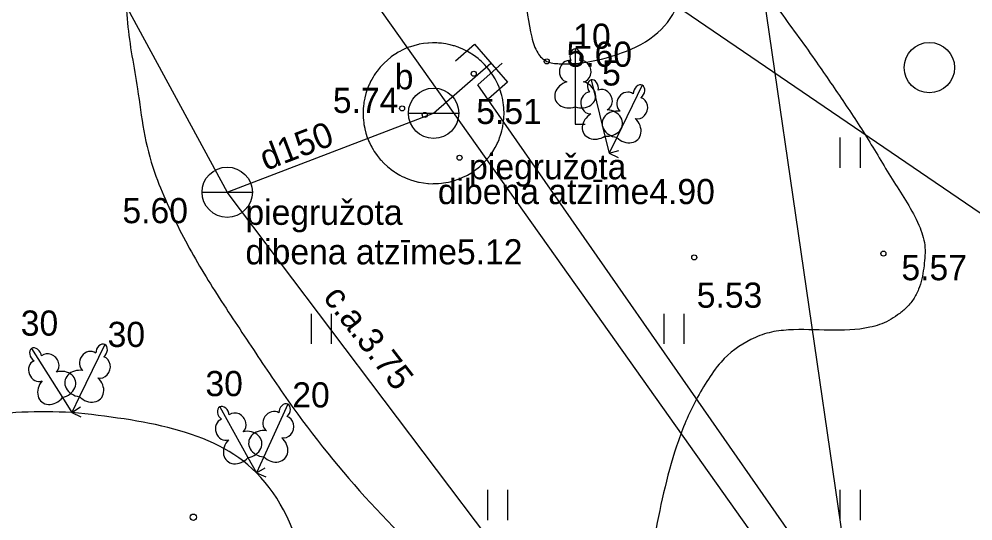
# Model space of a CAD drawing. Extents: x 519536 to 519949, y 326041 to 326519.
# Drawn here: x 519618.19 to 519637.13, y 326371.48 to 326381.46 of the extents above; entities that cross this region are included whole.
import ezdxf

# ---------------------------------------------------------------- set-up
doc = ezdxf.new("R2010")
doc.units = 0
for name, color, linetype in [('APGR_SARK_####_####_#', 7, 'Continuous'), ('BUVE_BDET_####_####_#', 7, 'Continuous'), ('BUVE_BDET_####_TKST_#', 7, 'Continuous'), ('ELEK_VADP_ZSPR_####_#', 7, 'Continuous'), ('RELJ_AATZ_####_TKST_#', 7, 'Continuous'), ('RELJ_ELEM_####_####_#', 7, 'Continuous'), ('RELJ_HORZ_PAMT_####_#', 7, 'Continuous'), ('RELJ_NOGA_####_####_#', 7, 'Continuous'), ('TERT_DIAM_####_TKST_#', 7, 'Continuous'), ('TERT_ELEM_####_####_#', 7, 'Continuous'), ('TERT_KONT_####_####_#', 7, 'Continuous'), ('UDTK_ELEM_####_####_#', 7, 'Continuous'), ('UDTK_ELEM_####_TKST_#', 7, 'Continuous'), ('UDTK_VADP_NEDR_####_#', 7, 'Continuous'), ('UDTK_VADP_UDEN_####_#', 7, 'Continuous'), ('UDTK_VADP_UDEN_TKST_#', 7, 'Continuous')]:
    doc.layers.add(name, color=color, linetype=linetype)

msp = doc.modelspace()

# ---------------------------------------------------------------- linework, layer by layer
at = {"layer": 'APGR_SARK_####_####_#'}
msp.add_line((519627.524, 326419.488), (519634.774, 326369.546), dxfattribs=at)
at = {"layer": 'BUVE_BDET_####_####_#'}
for points in [[(519625.753, 326380.812), (519625.724, 326380.796), (519625.667, 326380.761)], [(519625.843, 326380.857), (519625.802, 326380.838), (519625.753, 326380.812)], [(519625.935, 326380.895), (519625.883, 326380.875), (519625.843, 326380.857)], [(519626.03, 326380.927), (519625.966, 326380.907), (519625.935, 326380.895)], [(519626.126, 326380.952), (519626.051, 326380.933), (519626.03, 326380.927)], [(519626.225, 326380.97), (519626.137, 326380.954), (519626.126, 326380.952)], [(519626.324, 326380.98), (519626.313, 326380.98), (519626.225, 326380.97)], [(519626.424, 326380.983), (519626.402, 326380.984), (519626.324, 326380.98)], [(519626.524, 326380.98), (519626.491, 326380.982), (519626.424, 326380.983)], [(519626.623, 326380.969), (519626.579, 326380.975), (519626.524, 326380.98)], [(519626.721, 326380.951), (519626.667, 326380.963), (519626.623, 326380.969)], [(519626.818, 326380.927), (519626.754, 326380.945), (519626.721, 326380.951)], [(519626.913, 326380.895), (519626.84, 326380.921), (519626.818, 326380.927)], [(519627.006, 326380.857), (519627.006, 326380.857), (519626.924, 326380.892), (519626.913, 326380.895)], [(519627.095, 326380.812), (519627.085, 326380.818), (519627.006, 326380.857)], [(519627.181, 326380.761), (519627.162, 326380.774), (519627.095, 326380.812)], [(519625.507, 326380.642), (519625.442, 326380.582), (519625.434, 326380.574)], [(519625.585, 326380.705), (519625.576, 326380.698), (519625.507, 326380.642), (519625.507, 326380.642)], [(519625.667, 326380.761), (519625.649, 326380.75), (519625.585, 326380.705)], [(519627.263, 326380.704), (519627.236, 326380.724), (519627.181, 326380.761)], [(519627.34, 326380.642), (519627.307, 326380.671), (519627.263, 326380.704)], [(519627.413, 326380.573), (519627.374, 326380.612), (519627.34, 326380.642)], [(519625.366, 326380.5), (519625.324, 326380.449), (519625.304, 326380.423)], [(519625.434, 326380.574), (519625.381, 326380.517), (519625.366, 326380.5)], [(519627.482, 326380.5), (519627.437, 326380.55), (519627.413, 326380.573)], [(519627.545, 326380.423), (519627.496, 326380.484), (519627.482, 326380.5)], [(519625.196, 326380.255), (519625.18, 326380.226), (519625.151, 326380.165)], [(519625.247, 326380.341), (519625.223, 326380.303), (519625.196, 326380.255)], [(519625.304, 326380.423), (519625.271, 326380.378), (519625.247, 326380.341)], [(519627.602, 326380.341), (519627.602, 326380.341), (519627.551, 326380.414), (519627.545, 326380.423)], [(519627.652, 326380.255), (519627.647, 326380.265), (519627.602, 326380.341)], [(519627.697, 326380.165), (519627.688, 326380.186), (519627.652, 326380.255)], [(519625.113, 326380.073), (519625.108, 326380.063), (519625.081, 326379.978), (519625.081, 326379.978)], [(519625.151, 326380.165), (519625.141, 326380.145), (519625.113, 326380.073)], [(519627.735, 326380.073), (519627.724, 326380.104), (519627.697, 326380.165)], [(519627.767, 326379.978), (519627.754, 326380.021), (519627.735, 326380.073)], [(519625.056, 326379.882), (519625.042, 326379.805), (519625.039, 326379.783)], [(519625.081, 326379.978), (519625.058, 326379.892), (519625.056, 326379.882)], [(519627.791, 326379.881), (519627.779, 326379.936), (519627.767, 326379.978)], [(519627.809, 326379.783), (519627.799, 326379.849), (519627.791, 326379.881)], [(519625.028, 326379.684), (519625.025, 326379.628), (519625.025, 326379.584)], [(519625.039, 326379.783), (519625.03, 326379.717), (519625.028, 326379.684)], [(519627.82, 326379.684), (519627.813, 326379.761), (519627.809, 326379.783)], [(519627.824, 326379.584), (519627.821, 326379.673), (519627.82, 326379.684)], [(519625.025, 326379.584), (519625.025, 326379.54), (519625.028, 326379.484)], [(519625.028, 326379.484), (519625.03, 326379.451), (519625.039, 326379.385)], [(519627.809, 326379.385), (519627.813, 326379.407), (519627.82, 326379.484)], [(519627.82, 326379.484), (519627.821, 326379.495), (519627.824, 326379.584)], [(519625.039, 326379.385), (519625.042, 326379.363), (519625.056, 326379.286)], [(519627.791, 326379.287), (519627.799, 326379.319), (519627.809, 326379.385)], [(519625.056, 326379.286), (519625.058, 326379.276), (519625.081, 326379.19)], [(519625.081, 326379.19), (519625.081, 326379.19), (519625.108, 326379.105), (519625.113, 326379.095)], [(519627.735, 326379.095), (519627.754, 326379.147), (519627.767, 326379.19)], [(519627.767, 326379.19), (519627.779, 326379.232), (519627.791, 326379.287)], [(519625.113, 326379.095), (519625.141, 326379.023), (519625.151, 326379.003)], [(519625.151, 326379.003), (519625.18, 326378.942), (519625.196, 326378.913)], [(519625.196, 326378.913), (519625.223, 326378.865), (519625.247, 326378.827)], [(519627.602, 326378.827), (519627.647, 326378.903), (519627.652, 326378.913)], [(519627.652, 326378.913), (519627.688, 326378.982), (519627.697, 326379.003)], [(519627.697, 326379.003), (519627.724, 326379.064), (519627.735, 326379.095)], [(519625.247, 326378.827), (519625.271, 326378.79), (519625.304, 326378.745)], [(519625.304, 326378.745), (519625.324, 326378.719), (519625.366, 326378.668)], [(519627.482, 326378.668), (519627.496, 326378.684), (519627.545, 326378.745)], [(519627.545, 326378.745), (519627.551, 326378.754), (519627.602, 326378.827), (519627.602, 326378.827)], [(519625.366, 326378.668), (519625.381, 326378.651), (519625.434, 326378.594)], [(519625.434, 326378.594), (519625.442, 326378.586), (519625.507, 326378.526)], [(519627.34, 326378.526), (519627.374, 326378.556), (519627.413, 326378.595)], [(519627.413, 326378.595), (519627.437, 326378.618), (519627.482, 326378.668)], [(519625.507, 326378.526), (519625.507, 326378.526), (519625.576, 326378.47), (519625.585, 326378.463)], [(519625.585, 326378.463), (519625.649, 326378.418), (519625.667, 326378.407)], [(519625.667, 326378.407), (519625.724, 326378.372), (519625.753, 326378.356)], [(519625.753, 326378.356), (519625.802, 326378.33), (519625.843, 326378.311)], [(519627.006, 326378.311), (519627.085, 326378.35), (519627.095, 326378.356)], [(519627.095, 326378.356), (519627.162, 326378.394), (519627.181, 326378.407)], [(519627.181, 326378.407), (519627.236, 326378.444), (519627.263, 326378.464)], [(519627.263, 326378.464), (519627.307, 326378.497), (519627.34, 326378.526)], [(519625.843, 326378.311), (519625.883, 326378.293), (519625.935, 326378.273)], [(519625.935, 326378.273), (519625.966, 326378.261), (519626.03, 326378.241)], [(519626.03, 326378.241), (519626.051, 326378.235), (519626.126, 326378.216)], [(519626.126, 326378.216), (519626.137, 326378.214), (519626.225, 326378.198)], [(519626.225, 326378.198), (519626.225, 326378.198), (519626.313, 326378.188), (519626.324, 326378.188)], [(519626.324, 326378.188), (519626.402, 326378.184), (519626.424, 326378.185)], [(519626.424, 326378.185), (519626.491, 326378.186), (519626.524, 326378.188)], [(519626.524, 326378.188), (519626.579, 326378.193), (519626.623, 326378.199)], [(519626.623, 326378.199), (519626.667, 326378.205), (519626.721, 326378.217)], [(519626.721, 326378.217), (519626.754, 326378.223), (519626.818, 326378.241)], [(519626.818, 326378.241), (519626.84, 326378.247), (519626.913, 326378.273)], [(519626.913, 326378.273), (519626.924, 326378.276), (519627.006, 326378.311), (519627.006, 326378.311)]]:
    msp.add_lwpolyline(points, dxfattribs=at)
at = {"layer": 'ELEK_VADP_ZSPR_####_#'}
msp.add_lwpolyline([(519624.806, 326383.624), (519624.317, 326383.124), (519628.837, 326376.745), (519633.357, 326370.366), (519636.308, 326366.202)], dxfattribs=at)
at = {"layer": 'RELJ_ELEM_####_####_#'}
for centre in [(519628.671, 326380.615), (519627.222, 326380.37), (519625.8, 326379.68), (519626.249, 326379.55), (519626.94, 326378.7), (519635.356, 326376.795), (519631.6, 326376.719)]:
    msp.add_circle(centre, 0.05, dxfattribs=at)
at = {"layer": 'RELJ_HORZ_PAMT_####_#'}
msp.add_spline([(519627.567, 326390.536), (519627.439, 326390.463), (519626.198, 326389.853), (519625.058, 326389.287), (519624.874, 326389.151), (519624.795, 326389.064), (519624.721, 326388.967), (519624.639, 326388.783), (519624.643, 326388.596), (519624.9, 326388.196), (519625.507, 326387.801), (519626.121, 326387.441), (519627.362, 326386.783), (519628.592, 326386.136), (519629.784, 326385.418), (519630.266, 326385.105), (519630.736, 326384.778), (519631.195, 326384.434), (519631.645, 326384.073), (519631.868, 326383.825), (519632.043, 326383.538), (519632.202, 326383.243), (519632.36, 326382.949), (519632.536, 326382.666), (519632.896, 326382.158), (519633.264, 326381.656), (519633.633, 326381.154), (519633.994, 326380.647), (519634.551, 326379.835), (519635.084, 326379.012), (519635.594, 326378.171), (519636.084, 326377.305), (519636.182, 326376.913), (519636.178, 326376.707), (519636.157, 326376.505), (519636.056, 326376.085), (519635.954, 326375.889), (519635.802, 326375.707), (519635.638, 326375.575), (519635.465, 326375.464), (519635.086, 326375.33), (519634.285, 326375.272), (519633.473, 326375.277), (519633.087, 326375.223), (519632.727, 326375.088), (519632.132, 326374.64), (519631.848, 326374.25), (519631.611, 326373.838), (519631.248, 326372.965), (519630.793, 326371.1), (519630.353, 326369.239), (519630.204, 326368.798), (519630.11, 326368.584), (519630.01, 326368.37), (519629.786, 326367.959), (519629.515, 326367.575), (519628.999, 326367.103), (519628.235, 326366.707), (519627.434, 326366.463), (519625.042, 326366.078), (519622.618, 326365.897), (519620.206, 326365.982), (519619.61, 326366.058), (519619.019, 326366.149), (519617.849, 326366.397), (519616.935, 326366.637)], degree=3, dxfattribs=at)
at = {"layer": 'RELJ_NOGA_####_####_#'}
msp.add_spline([(519633.005, 326382.956), (519639.907, 326381.113), (519643.418, 326377.883), (519651.003, 326389.626), (519657.231, 326401.681), (519665.468, 326403.519), (519679.321, 326396.739), (519683.853, 326390.018), (519690.141, 326388.505), (519700.416, 326393.799)], degree=3, dxfattribs=at)
at = {"layer": 'TERT_ELEM_####_####_#'}
for p, q in [((519629.237, 326379.712), (519629.237, 326379.365)), ((519629.237, 326379.365), (519629.437, 326379.365)), ((519629.827, 326379.13), (519629.91, 326378.793)), ((519630.062, 326379.105), (519629.91, 326378.793)), ((519634.5, 326378.5), (519634.5, 326379.1)), ((519634.9, 326378.5), (519634.9, 326379.1)), ((519629.91, 326378.793), (519630.104, 326378.841)), ((519629.91, 326378.793), (519630.09, 326378.705)), ((519624, 326375), (519624, 326375.6)), ((519624.4, 326375), (519624.4, 326375.6)), ((519631, 326375), (519631, 326375.6)), ((519631.4, 326375), (519631.4, 326375.6)), ((519619.056, 326373.934), (519619.241, 326373.64)), ((519619.393, 326373.952), (519619.241, 326373.64)), ((519619.241, 326373.64), (519619.41, 326373.747)), ((519619.241, 326373.64), (519619.421, 326373.553)), ((519622.739, 326372.741), (519622.908, 326372.438)), ((519623.051, 326372.754), (519622.908, 326372.438)), ((519622.908, 326372.438), (519623.083, 326372.536)), ((519622.908, 326372.438), (519623.09, 326372.355)), ((519627.5, 326371.5), (519627.5, 326372.1)), ((519627.9, 326371.5), (519627.9, 326372.1)), ((519634.5, 326371.5), (519634.5, 326372.1)), ((519634.9, 326371.5), (519634.9, 326372.1))]:
    msp.add_line(p, q, dxfattribs=at)
for points in [[(519629.237, 326380.865), (519629.237, 326379.712)], [(519629.327, 326380.633), (519629.326, 326380.634)], [(519629.553, 326380.25), (519629.827, 326379.13)], [(519629.695, 326380.045), (519629.694, 326380.046)], [(519630.568, 326380.141), (519630.062, 326379.105)], [(519630.546, 326379.893), (519630.546, 326379.894)], [(519619.897, 326374.989), (519619.393, 326373.952)], [(519618.442, 326374.909), (519619.056, 326373.934)], [(519618.641, 326374.76), (519618.64, 326374.761)], [(519619.876, 326374.741), (519619.876, 326374.742)], [(519623.528, 326373.804), (519623.051, 326372.754)], [(519622.177, 326373.748), (519622.739, 326372.741)], [(519622.368, 326373.588), (519622.367, 326373.589)], [(519623.514, 326373.555), (519623.513, 326373.556)]]:
    msp.add_lwpolyline(points, dxfattribs=at)
for centre, radius in [((519636.269, 326380.491), 0.5), ((519621.654, 326371.555), 0.064)]:
    msp.add_circle(centre, radius, dxfattribs=at)
for centre, major_axis, ratio, start_param, end_param in [((519629.237, 326380.715), (0, -0.15), 0.707107, 3.14537, 5.287485), ((519629.237, 326380.715), (0, -0.15), 0.707107, 0.995701, 3.137816), ((519629.109, 326380.42), (-0.039, -0.212), 0.861323, 3.141593, 6.283185), ((519629.365, 326380.42), (0.039, -0.212), 0.861323, 0, 3.141593), ((519629.589, 326380.104), (0.036, -0.146), 0.707107, 3.14537, 5.287485), ((519629.588, 326380.104), (0.036, -0.146), 0.707107, 0.995701, 3.137816), ((519629.147, 326379.958), (0.307, 0.095), 0.814445, 1.570796, 4.752015), ((519629.327, 326379.958), (-0.307, 0.095), 0.814445, 1.531171, 4.712389), ((519629.783, 326379.848), (0.088, -0.197), 0.861323, 0, 3.141593), ((519630.503, 326380.006), (-0.066, -0.135), 0.707107, 3.14537, 5.287485), ((519630.502, 326380.006), (-0.066, -0.135), 0.707107, 0.995701, 3.137816), ((519629.534, 326379.787), (0.013, -0.216), 0.861323, 3.141593, 6.283185), ((519630.258, 326379.798), (-0.128, -0.174), 0.861323, 3.141593, 6.283185), ((519630.488, 326379.685), (-0.058, -0.208), 0.861323, 0, 3.141593), ((519629.682, 326379.347), (0.275, 0.165), 0.814445, 1.570796, 4.752015), ((519630.09, 326379.365), (0.317, -0.049), 0.814445, 1.570796, 4.752015), ((519629.856, 326379.39), (-0.321, 0.019), 0.814445, 1.531171, 4.712389), ((519630.251, 326379.287), (-0.234, 0.22), 0.814445, 1.531171, 4.712389), ((519619.832, 326374.854), (-0.066, -0.135), 0.707107, 3.14537, 5.287485), ((519619.831, 326374.854), (-0.066, -0.135), 0.707107, 0.995701, 3.137816), ((519618.522, 326374.783), (0.08, -0.127), 0.707107, 3.14537, 5.287485), ((519618.521, 326374.782), (0.08, -0.127), 0.707107, 0.995701, 3.137816), ((519618.787, 326374.601), (0.146, -0.159), 0.861323, 0, 3.141593), ((519619.587, 326374.645), (-0.128, -0.174), 0.861323, 3.141593, 6.283185), ((519618.57, 326374.464), (0.08, -0.2), 0.861323, 3.141593, 6.283185), ((519619.818, 326374.533), (-0.058, -0.208), 0.861323, 0, 3.141593), ((519619.001, 326374.189), (-0.31, -0.083), 0.814445, 1.531171, 4.712389), ((519619.42, 326374.212), (0.318, -0.049), 0.814445, 1.570796, 4.752015), ((519618.849, 326374.094), (0.209, 0.244), 0.814445, 1.570796, 4.752015), ((519619.581, 326374.134), (-0.234, 0.22), 0.814445, 1.531171, 4.712389), ((519623.467, 326373.667), (-0.062, -0.137), 0.707107, 3.14537, 5.287485), ((519623.466, 326373.667), (-0.062, -0.137), 0.707107, 0.995701, 3.137816), ((519622.25, 326373.617), (0.073, -0.131), 0.707107, 3.14537, 5.287485), ((519622.249, 326373.616), (0.073, -0.131), 0.707107, 0.995701, 3.137816), ((519622.505, 326373.422), (0.137, -0.167), 0.861323, 0, 3.141593), ((519623.228, 326373.452), (-0.123, -0.177), 0.861323, 3.141593, 6.283185), ((519622.281, 326373.297), (0.07, -0.204), 0.861323, 3.141593, 6.283185), ((519623.461, 326373.346), (-0.053, -0.209), 0.861323, 0, 3.141593), ((519622.697, 326372.999), (-0.314, -0.067), 0.814445, 1.531171, 4.712389), ((519623.072, 326373.015), (0.319, -0.04), 0.814445, 1.570796, 4.752015), ((519622.541, 326372.912), (0.221, 0.233), 0.814445, 1.570796, 4.752015), ((519623.235, 326372.941), (-0.24, 0.213), 0.814445, 1.531171, 4.712389)]:
    msp.add_ellipse(centre, major_axis=major_axis, ratio=ratio, start_param=start_param, end_param=end_param, dxfattribs=at)
at = {"layer": 'TERT_KONT_####_####_#'}
msp.add_line((519640.6, 326375.326), (519631.246, 326381.713), dxfattribs=at)
for points in [[(519617.458, 326408.853), (519614.406, 326408.421), (519613.425, 326408.287), (519612.935, 326408.209), (519612.691, 326408.164), (519612.446, 326408.112), (519612.195, 326407.934), (519612.05, 326407.611), (519611.983, 326407.242), (519611.962, 326406.931), (519612.022, 326406.495), (519612.212, 326406.065), (519612.91, 326405.218), (519615.027, 326403.551), (519617.072, 326401.861), (519617.681, 326400.987), (519617.806, 326400.081), (519617.632, 326399.669), (519617.334, 326399.244), (519617.028, 326398.808), (519616.827, 326398.364), (519616.67, 326397.679), (519616.553, 326396.945), (519616.589, 326395.862), (519616.631, 326395.694), (519616.687, 326395.531), (519617.235, 326394.482), (519617.976, 326393.521), (519619.807, 326391.769), (519621.72, 326390.081), (519622.563, 326389.2), (519623.255, 326388.264), (519623.656, 326387.3), (519623.912, 326386.211), (519624.184, 326385.124), (519624.631, 326384.166), (519625.267, 326383.787), (519626.155, 326383.728), (519627.059, 326383.732), (519627.444, 326383.678), (519627.746, 326383.543), (519628.081, 326382.913), (519628.235, 326381.979), (519628.375, 326381.094), (519628.493, 326380.782), (519628.671, 326380.615), (519628.921, 326380.569), (519629.257, 326380.576), (519630.055, 326380.748), (519630.805, 326381.127), (519631.246, 326381.713), (519631.293, 326381.95), (519631.303, 326382.19), (519631.26, 326382.673), (519631.202, 326383.156), (519631.2, 326383.513), (519631.215, 326383.631), (519631.33, 326384.243), (519631.478, 326384.85), (519631.668, 326385.449), (519631.908, 326386.037), (519633.023, 326386.993), (519634.679, 326387.43), (519636.274, 326387.881), (519637.205, 326388.884), (519637.297, 326389.248), (519637.376, 326389.616), (519637.495, 326390.362), (519637.585, 326391.875), (519637.494, 326393.388), (519637.245, 326394.868), (519636.946, 326396.104), (519636.617, 326397.338), (519636.287, 326398.572), (519635.986, 326399.809), (519635.636, 326401.492), (519635.353, 326403.202), (519635.177, 326404.912), (519635.14, 326405.758), (519635.137, 326406.178), (519635.144, 326406.594), (519635.346, 326407.323), (519635.839, 326407.935), (519637.329, 326408.962), (519638.871, 326409.997), (519639.43, 326410.617), (519639.723, 326411.359), (519641.003, 326419.41)], [(519623.75, 326386.05), (519623.59, 326385.967), (519622.591, 326385.369), (519621.671, 326384.623), (519620.923, 326383.731), (519620.641, 326383.229), (519620.527, 326382.964), (519620.435, 326382.69), (519620.346, 326381.381), (519620.545, 326380.069), (519620.67, 326379.235), (519620.882, 326378.41), (519621.133, 326377.793), (519621.419, 326377.196), (519622.081, 326376.052), (519622.801, 326374.955), (519623.536, 326373.869), (519625.172, 326371.841), (519627.026, 326369.969), (519628.838, 326368.064), (519629.649, 326367.041), (519630.016, 326366.501), (519630.353, 326365.939), (519630.879, 326364.406), (519630.956, 326362.743), (519630.728, 326361.043), (519630.342, 326359.4), (519629.857, 326357.655), (519629.244, 326355.981), (519628.357, 326354.369), (519627.764, 326353.583), (519627.423, 326353.195), (519627.049, 326352.81), (519626.009, 326351.982), (519624.891, 326351.435), (519623.765, 326351.197), (519623.221, 326351.201), (519622.699, 326351.292), (519620.583, 326352.067), (519618.508, 326353.226), (519616.494, 326354.729), (519615.516, 326355.597), (519614.561, 326356.536), (519612.449, 326358.913), (519610.726, 326361.321), (519609.339, 326363.865), (519608.756, 326365.219), (519608.237, 326366.647), (519606.835, 326371.931), (519606.054, 326377.25), (519605.784, 326382.571), (519605.805, 326385.222), (519605.913, 326387.86), (519606.057, 326391.001), (519606.181, 326392.606), (519606.268, 326393.407), (519606.362, 326394.208), (519606.478, 326394.977), (519606.646, 326395.736), (519606.865, 326396.486), (519607.137, 326397.227), (519607.808, 326398.595), (519608.695, 326399.809), (519612.994, 326404.58)], [(519619.241, 326373.64), (519622.908, 326372.438), (519623.589, 326368.29), (519614.225, 326366.678), (519614.557, 326370.916), (519617.305, 326373.507), (519619.241, 326373.64)]]:
    msp.add_spline(points, degree=3, dxfattribs=at)
at = {"layer": 'UDTK_ELEM_####_####_#'}
for p, q in [((519625.925, 326379.584), (519626.925, 326379.584)), ((519621.826, 326378.015), (519622.826, 326378.015))]:
    msp.add_line(p, q, dxfattribs=at)
msp.add_lwpolyline([(519626.858, 326380.626), (519627.235, 326380.955), (519627.892, 326380.201), (519627.515, 326379.872)], dxfattribs=at)
for centre in [(519626.425, 326379.584), (519622.326, 326378.015)]:
    msp.add_circle(centre, 0.5, dxfattribs=at)
at = {"layer": 'UDTK_VADP_NEDR_####_#'}
for p, q in [((519627.3, 326380.151), (519627.786, 326380.578)), ((519636.278, 326367.261), (519627.3, 326380.151))]:
    msp.add_line(p, q, dxfattribs=at)
at = {"layer": 'UDTK_VADP_UDEN_####_#'}
for points in [[(519595.269, 326422.378), (519610.403, 326399.994), (519622.325, 326378.015)], [(519626.424, 326379.584), (519627.563, 326380.578)], [(519622.325, 326378.015), (519626.424, 326379.584)], [(519635.833, 326360.1), (519622.325, 326378.015)]]:
    msp.add_lwpolyline(points, dxfattribs=at)

# ---------------------------------------------------------------- texts
at = {"layer": 'BUVE_BDET_####_TKST_#'}
msp.add_text('b', height=0.5, dxfattribs=at).set_placement((519625.652, 326380.06))
at = {"layer": 'RELJ_AATZ_####_TKST_#'}
for s, p in [('5.60', (519629.064, 326380.508)), ('5.51', (519627.272, 326379.37)), ('5.57', (519635.714, 326376.265)), ('5.53', (519631.65, 326375.719))]:
    msp.add_text(s, height=0.5, dxfattribs=at).set_placement(p)
at = {"layer": 'TERT_DIAM_####_TKST_#'}
for s, p in [(' 10', (519629.012, 326380.865)), (' 5', (519629.584, 326380.135)), (' 30', (519618.041, 326375.164)), (' 30', (519619.766, 326374.939)), (' 30', (519621.708, 326373.962)), (' 20', (519623.433, 326373.737))]:
    msp.add_text(s, height=0.5, dxfattribs=at).set_placement(p)
at = {"layer": 'UDTK_ELEM_####_TKST_#'}
for s, p in [('5.74', (519624.424, 326379.59)), ('piegružota', (519627.131, 326378.272)), ('dibena atzīme4.90', (519626.509, 326377.778)), ('5.60', (519620.246, 326377.399)), ('piegružota', (519622.688, 326377.366)), ('dibena atzīme5.12', (519622.688, 326376.581))]:
    msp.add_text(s, height=0.5, dxfattribs=at).set_placement(p)
at = {"layer": 'UDTK_VADP_UDEN_TKST_#'}
for s, rotation, p in [('d150', 20.9457, (519623.092, 326378.437)), ('c.a.3.75', 307.7036, (519624.213, 326375.92))]:
    msp.add_text(s, height=0.5, rotation=rotation, dxfattribs=at).set_placement(p)

doc.saveas('drawing.dxf')
